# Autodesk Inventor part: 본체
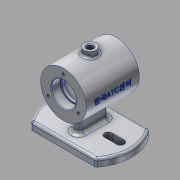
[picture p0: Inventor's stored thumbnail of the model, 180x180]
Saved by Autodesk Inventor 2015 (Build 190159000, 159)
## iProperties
Created: 2017-12
Part Number: 본체
Material: 알루미늄 6061
Document SubType Name: Modeling
Designer: SCD-A03
Density: 2.7 g/cm^3
Appearance: 알루미늄 - 평지
Mass: 465.966 g
Surface Area: 486.474 cm^2
Volume: 172.58 cm^3
Author: SCD-A03
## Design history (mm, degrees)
sketch "스케치1"
  geometry: C1 r 30 at (0, 0); 1 further point
  constraints: 1 centre point, 1 coincident
  dimensions: "d0" = 60 diameter of C1
extrude "돌출1" new body sketch "스케치1" stored distance "d1" = 70; taper "d2" = 0 deg
node "작업 평면1"
sketch "스케치2"
  geometry: L1 (-42.426, 35)-(42.426, 35); L2 (42.426, -35)-(-42.426, -35); A1 r 55 centre (0, 0) between (-42.426, 35) and (-42.426, -35); A2 r 55 centre (0, 0) between (42.426, -35) and (42.426, 35); 2 further points
  constraints: 4 end point, 4 point on circle, 2 centre point, 1 coincident, 1 horizontal, 1 horizontal alignment, 1 parallel
  dimensions: "d5" = 70 distance between parallel lines of L2 L1; "d6" = 35 distance from line of point (0, 0) L1
extrude "돌출2" join sketch "스케치2" distance "d7" = 10; taper "d8" = 0 deg
sketch "스케치3"
  geometry: L1 (-5, 15.086)-(5, 15.086); L2 (5, 15.086)-(5, -14.914); L3 (5, -14.914)-(-5, -14.914); L4 (-5, -14.914)-(-5, 15.086); A1 r 55 centre (0, 0) between (-42.426, 35) and (-42.426, -35) reference; 3 further points
  constraints: 8 end point, 3 horizontal alignment, 2 midpoint, 2 parallel, 1 horizontal, 1 perpendicular, 4 other
  dimensions: "d18" = 5 distance from line of A1.centre L4; "d19" = 10 distance between parallel lines of L2 L4; "d20" = 30 distance of L1.end L2.end
extrude "돌출3" join sketch "스케치3" stored distance "d12" = 10; taper "d13" = 0 deg
sketch "스케치5"
  geometry: L1 (40, 5)-(24, 5); L2 (24, 5)-(24, -5); L3 (24, -5)-(40, -5); L4 (40, -5)-(40, 5); L5 (0, 0)-(0, -14.914); L6 (-24, 5)-(-24, -5); L7 (-40, 5)-(-24, 5); L8 (-24, -5)-(-40, -5); L9 (-40, -5)-(-40, 5); A1 r 5 centre (0, -14.914) between (-5, -14.914) and (5, -14.914) reference; A2 r 55 centre (0, 0) between (-42.426, 35) and (-42.426, -35) reference; A3 r 55 centre (0, 0) between (42.426, -35) and (42.426, 35) reference; 6 further points
  constraints: 18 end point, 7 symmetric about line, 4 vertical alignment, 3 vertical, 2 coincident, 2 midpoint, 2 parallel, 1 horizontal, 1 horizontal alignment, 1 perpendicular, 8 other
  dimensions: "d21" = 10 distance of L3.end L1.start; "d22" = 24 distance from line of A2.centre L2; "d23" = 16 distance of L2.end L3.end
extrude "돌출4" cut sketch "스케치5" distance "d24" = 10; taper "d25" = 0 deg
sketch "스케치6"
  geometry: C1 r 30 at (0, 0) reference; C2 r 16 at (0, 0)
  constraints: 1 centre point, 1 coincident
  dimensions: "d26" = 32 diameter of C2
extrude "돌출5" cut sketch "스케치6" distance "d27" = 12; taper "d28" = 0 deg
sketch "스케치7"
  geometry: C1 r 16 at (0, 0) reference; C2 r 14 at (0, 0)
  constraints: 1 centre point, 1 coincident
  dimensions: "d29" = 28 diameter of C2
extrude "돌출6" cut sketch "스케치7" distance "d30" = 3; taper "d31" = 0 deg
sketch "스케치8"
  geometry: C1 r 14 at (0, 0) reference; C2 r 25 at (0, 0)
  constraints: 1 centre point, 1 coincident
  dimensions: "d32" = 50 diameter of C2
extrude "돌출7" cut sketch "스케치8" distance "d33" = 40; taper "d34" = 0 deg
node "작업 평면2"
node "작업 평면3"
sketch "스케치9"
  geometry: C1 r 8 at (0, 0); 1 further point
  constraints: 1 centre point, 1 coincident
  dimensions: "d36" = 16 diameter of C1
extrude "돌출8" join sketch "스케치9" stored distance "d37" = 40; taper "d38" = 0 deg
hole "구멍1" diameter "d41" = 8; stored, may be unused: countersink angle "d45" = 90 deg, drill point angle "d47" = 118 deg; dims "d39" = 10, "d40" = 10, "d42" = 6, "d43" = 4, "d44" = 2, "d46" = 20
sketch "스케치10" dims "d48" = 46
  geometry: C1 r 30 at (0, 0) reference; 2 further points
  constraints: 1 coincident, 1 vertical alignment, 2 other
hole "구멍2" sketch "스케치10" at (0, 23) diameter "d49" = 3.242; stored, may be unused: countersink angle "d53" = 90 deg, drill point angle "d55" = 118 deg; dims "d50" = 8, "d51" = 4, "d52" = 2, "d54" = 10
node "작업 평면4"
sketch "스케치11"
  geometry: L1 (-35, 30)-(35, 30) reference; 2 further points
  constraints: 1 other
  dimensions: "d60" = 30 distance from line of point (0, 0) L1
feature "엠보싱1" sketch "스케치11" dims "d18" = 5, "d19" = 10, "d20" = 30, "d61" = 0.5, "d62" = 0
fillet "모깎기1" dims "d63" = 5
fillet "모깎기2" dims "d64" = 3
fillet "모깎기3" dims "d65" = 3
fillet "모깎기4" dims "d66" = 3
chamfer "모따기1" distance "d67" = 1; stored, may be unused: second distance "d68" = 2, angle "d69" = 45 deg
fillet "모깎기5" dims "d70" = 3
fillet "모깎기6" dims "d71" = 0.3
node "솔리드1"
mirror "대칭1"
pattern_circular "원형 패턴1" dims angle "d57" = 360 deg
mirror "대칭2"
other parameters: "d3" = -62, "d35" = 37, "d59" = 35
